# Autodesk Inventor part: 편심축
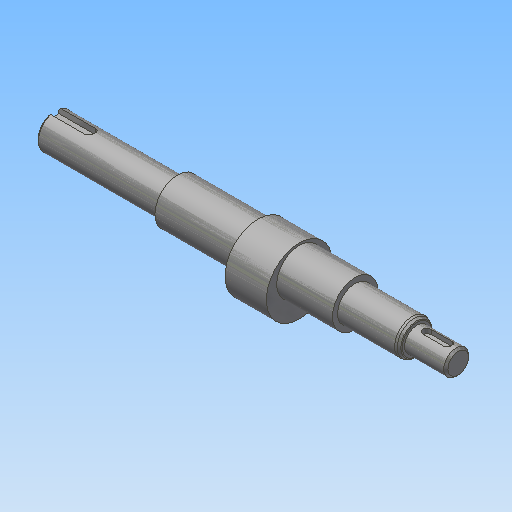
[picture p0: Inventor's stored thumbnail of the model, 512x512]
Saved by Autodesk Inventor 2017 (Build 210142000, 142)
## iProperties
Created: 2016-05
Part Number: 편심축
Document SubType Name: Modeling
Designer: mduedu
Density: 7.86 g/cm^3
Material: 강철, 연강
Appearance: 강철
Author: mduedu
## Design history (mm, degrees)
sketch "스케치1"
  geometry: L1 (-38, 11)-(-38, 8.5); L2 (48, 11)-(48, 8.5); L3 (-98, 0)-(98, 0); L4 (-38, 11)-(48, 11); L5 (48, 11)-(48, 8.5); L6 (-38, 11)-(-38, 8.5); L7 (-38, 8.5)-(-98, 8.5); L8 (-98, 8.5)-(-98, 0); L9 (48, 8.5)-(78, 8.5); L10 (98, 6)-(98, 0); L11 (78, 8.5)-(78, 6); L12 (78, 6)-(98, 6); 1 further point
  constraints: 24 end point, 9 perpendicular, 2 midpoint, 1 collinear, 1 horizontal
  dimensions: "d0" = 22 diameter of L4 L3; "d1" = 17 diameter of L7 L3; "d2" = 60 distance between parallel lines of L8 L1; "d3" = 50 distance between parallel lines of L10 L2; "d4" = 12 diameter of L12 L3; "d5" = 20 distance between parallel lines of L10 L11; "d29" = 86 distance of L1.start L2.start
revolve "회전1" stored, may be unused: angle "d6" = 90 deg
node "작업 평면7"
node "작업 평면9"
sketch "스케치2"
  geometry: C1 r 11 at (0, 0); C2 r 16 at (0, -4); C3 r 11 at (0, 0); 2 further points
  constraints: 3 centre point, 2 coincident, 1 concentric, 1 vertical alignment
  dimensions: "d9" = 4 distance of point (0, 0) C2.centre; "d10" = 32 diameter of C2
extrude "돌출1" join sketch "스케치2" stored distance "d11" = 20; taper "d12" = 0 deg
chamfer "모따기2" distance "d32" = 1; stored, may be unused: second distance "d33" = 2, angle "d34" = 45 deg
node "작업 평면4"
sketch "스케치4"
  geometry: L1 (-5, 2)-(5, 2); L2 (5, -2)-(-5, -2); L3 (-10, -5)-(-10, 5) reference; A1 r 2 centre (5, 0) between (5, -2) and (5, 2); A2 r 2 centre (-5, 0) between (-5, 2) and (-5, -2); 2 further points
  constraints: 4 end point, 4 point on circle, 4 tangent, 2 centre point, 2 horizontal alignment, 1 midpoint, 1 parallel
  dimensions: "d20" = 4 distance between parallel lines of L2 L1; "d21" = 14 dimension on A1 A2; "d35" = 3 distance edge to line of A2 L3
extrude "돌출3" cut sketch "스케치4" distance "d23" = 2.5; taper "d24" = 0 deg
node "작업 평면5"
sketch "스케치5"
  geometry: L1 (30, 2.5)-(12.5, 2.5); L2 (12.5, -2.5)-(30, -2.5); L3 (30, 7.5)-(30, -7.5) reference; A1 r 2.5 centre (12.5, 0) between (12.5, 2.5) and (12.5, -2.5); 2 further points
  constraints: 4 end point, 2 point on circle, 2 point on line, 2 tangent, 1 centre point, 1 horizontal, 1 horizontal alignment, 1 midpoint
  dimensions: "d25" = 5 distance between parallel lines of L2 L1; "d36" = 20 dimension on A1 L3
extrude "돌출4" cut sketch "스케치5" distance "d27" = 3; taper "d28" = 0 deg
chamfer "모따기3" distance "d37" = 1.82; stored, may be unused: second distance "d38" = 2, angle "d39" = 30 deg
fillet "모깎기1" dims "d40" = 2, "d41" = 0.5
node "솔리드1"
other parameters: "d31" = -37
